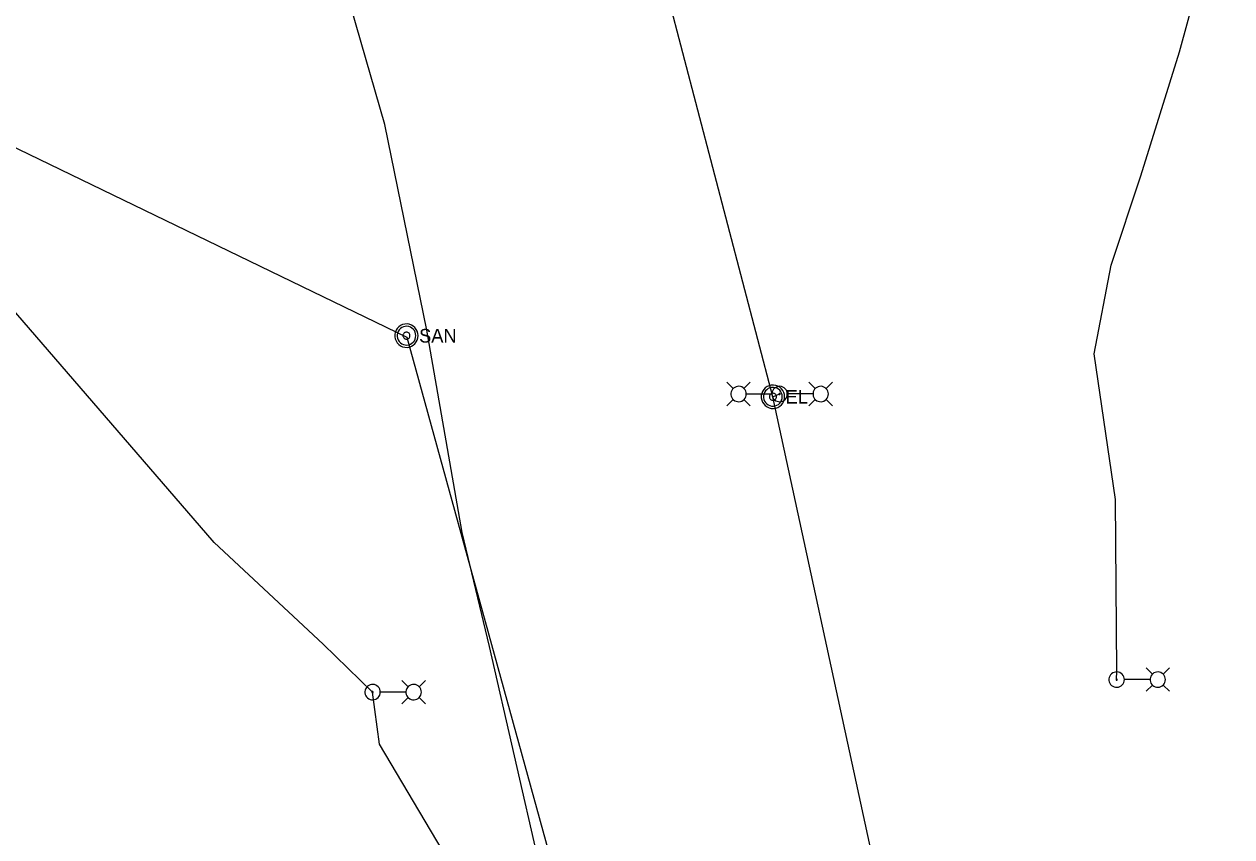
# Model space of a CAD drawing. Extents: x 600849 to 606371, y 330010 to 403088.
# Drawn here: x 603977.3 to 604318, y 348996 to 349225.2 of the extents above; entities that cross this region are included whole.
import ezdxf

# ---------------------------------------------------------------- set-up
doc = ezdxf.new("R2010")
doc.units = 0
for name, color, linetype in [('E_FTMS_Conduit', 7, 'Continuous'), ('E_LTG', 7, 'Continuous'), ('E_LTG_CID', 7, 'Continuous'), ('E_UTL_E', 7, 'Continuous'), ('E_UTL_E_UG', 7, 'Continuous'), ('E_UTL_SAN', 7, 'Continuous'), ('E_UTL_SAN_UG', 7, 'Continuous')]:
    doc.layers.add(name, color=color, linetype=linetype)

msp = doc.modelspace()

# ---------------------------------------------------------------- linework, layer by layer
at = {"layer": 'E_FTMS_Conduit'}
msp.add_lwpolyline([(604122.74, 348988.04), (604108.56, 349049.67), (604100.88, 349081.84), (604090.92, 349138.93), (604079.09, 349196.91), (604056.03, 349276.86), (604043.16, 349350.52), (604043.52, 349350.57), (604038.65, 349379.99), (604027.8, 349419.58), (604014.43, 349447.39), (603999.06, 349483.4), (603987.98, 349514.15), (603982.63, 349526.67)], dxfattribs=at)
at = {"layer": 'E_LTG'}
for points in [[(604177.34, 349122.43), (604175.57, 349124.21)], [(604181.04, 349120.91), (604181, 349121.32), (604180.89, 349121.71), (604180.7, 349122.08), (604180.44, 349122.41), (604180.13, 349122.68), (604179.77, 349122.89), (604179.38, 349123.02), (604178.97, 349123.08), (604178.56, 349123.06), (604178.16, 349122.96), (604177.78, 349122.79), (604177.44, 349122.55), (604177.16, 349122.25), (604176.93, 349121.9), (604176.78, 349121.52), (604176.7, 349121.11), (604176.7, 349120.7), (604176.78, 349120.29), (604176.93, 349119.91), (604177.16, 349119.56), (604177.44, 349119.26), (604177.78, 349119.02), (604178.16, 349118.85), (604178.56, 349118.75), (604178.97, 349118.73), (604179.38, 349118.79), (604179.77, 349118.93), (604180.13, 349119.13), (604180.44, 349119.4), (604180.7, 349119.73), (604180.89, 349120.1), (604181, 349120.49), (604181.04, 349120.91)], [(604180.39, 349122.43), (604182.17, 349124.21)], [(604192.61, 349120.91), (604192.57, 349121.32), (604192.45, 349121.71), (604192.26, 349122.08), (604192.01, 349122.41), (604191.69, 349122.68), (604191.34, 349122.88), (604190.95, 349123.02), (604190.54, 349123.08), (604190.12, 349123.06), (604189.72, 349122.96), (604189.34, 349122.79), (604189.01, 349122.55), (604188.72, 349122.25), (604188.5, 349121.9), (604188.35, 349121.52), (604188.27, 349121.11), (604188.27, 349120.7), (604188.35, 349120.29), (604188.5, 349119.91), (604188.72, 349119.56), (604189.01, 349119.26), (604189.34, 349119.02), (604189.72, 349118.85), (604190.12, 349118.75), (604190.54, 349118.73), (604190.95, 349118.79), (604191.34, 349118.93), (604191.69, 349119.13), (604192.01, 349119.4), (604192.26, 349119.73), (604192.45, 349120.1), (604192.57, 349120.49), (604192.61, 349120.91)], [(604200.51, 349122.43), (604198.74, 349124.21)], [(604204.21, 349120.91), (604204.17, 349121.32), (604204.06, 349121.71), (604203.87, 349122.08), (604203.61, 349122.41), (604203.3, 349122.68), (604202.94, 349122.88), (604202.55, 349123.02), (604202.14, 349123.08), (604201.73, 349123.06), (604201.32, 349122.96), (604200.95, 349122.79), (604200.61, 349122.55), (604200.33, 349122.25), (604200.1, 349121.9), (604199.95, 349121.52), (604199.87, 349121.11), (604199.87, 349120.7), (604199.95, 349120.29), (604200.1, 349119.91), (604200.33, 349119.56), (604200.61, 349119.26), (604200.95, 349119.02), (604201.32, 349118.85), (604201.73, 349118.75), (604202.14, 349118.73), (604202.55, 349118.79), (604202.94, 349118.93), (604203.3, 349119.13), (604203.61, 349119.4), (604203.87, 349119.73), (604204.06, 349120.1), (604204.17, 349120.49), (604204.21, 349120.91)], [(604203.56, 349122.43), (604205.34, 349124.21)], [(604181.08, 349120.91), (604188.26, 349120.91)], [(604190.6, 349120.91), (604190.6, 349120.94), (604190.59, 349120.97), (604190.57, 349121), (604190.55, 349121.02), (604190.53, 349121.04), (604190.5, 349121.06), (604190.47, 349121.07), (604190.44, 349121.07), (604190.41, 349121.07), (604190.38, 349121.06), (604190.35, 349121.05), (604190.32, 349121.03), (604190.3, 349121.01), (604190.28, 349120.98), (604190.27, 349120.95), (604190.27, 349120.92), (604190.27, 349120.89), (604190.27, 349120.86), (604190.28, 349120.83), (604190.3, 349120.8), (604190.32, 349120.78), (604190.35, 349120.76), (604190.38, 349120.75), (604190.41, 349120.74), (604190.44, 349120.74), (604190.47, 349120.74), (604190.5, 349120.75), (604190.53, 349120.77), (604190.55, 349120.79), (604190.57, 349120.82), (604190.59, 349120.84), (604190.6, 349120.87), (604190.6, 349120.91)], [(604199.82, 349120.91), (604192.65, 349120.91)], [(604177.34, 349119.38), (604175.57, 349117.61)], [(604180.39, 349119.38), (604182.17, 349117.61)], [(604200.51, 349119.38), (604198.74, 349117.61)], [(604203.56, 349119.38), (604205.34, 349117.61)], [(604287.72, 349040.34), (604287.68, 349040.75), (604287.56, 349041.15), (604287.37, 349041.52), (604287.11, 349041.84), (604286.8, 349042.11), (604286.44, 349042.32), (604286.05, 349042.45), (604285.64, 349042.51), (604285.23, 349042.49), (604284.83, 349042.39), (604284.45, 349042.22), (604284.12, 349041.98), (604283.83, 349041.68), (604283.61, 349041.34), (604283.45, 349040.95), (604283.37, 349040.55), (604283.37, 349040.13), (604283.45, 349039.73), (604283.61, 349039.34), (604283.83, 349038.99), (604284.12, 349038.69), (604284.45, 349038.45), (604284.83, 349038.28), (604285.23, 349038.19), (604285.64, 349038.17), (604286.05, 349038.22), (604286.44, 349038.36), (604286.8, 349038.57), (604287.11, 349038.84), (604287.37, 349039.16), (604287.56, 349039.53), (604287.68, 349039.93), (604287.72, 349040.34)], [(604295.62, 349041.86), (604293.84, 349043.64)], [(604299.32, 349040.34), (604299.28, 349040.75), (604299.16, 349041.15), (604298.97, 349041.52), (604298.72, 349041.84), (604298.41, 349042.11), (604298.05, 349042.32), (604297.66, 349042.45), (604297.25, 349042.51), (604296.83, 349042.49), (604296.43, 349042.39), (604296.06, 349042.22), (604295.72, 349041.98), (604295.43, 349041.68), (604295.21, 349041.34), (604295.06, 349040.95), (604294.98, 349040.55), (604294.98, 349040.13), (604295.06, 349039.73), (604295.21, 349039.34), (604295.43, 349038.99), (604295.72, 349038.69), (604296.06, 349038.45), (604296.43, 349038.28), (604296.83, 349038.19), (604297.25, 349038.17), (604297.66, 349038.22), (604298.05, 349038.36), (604298.41, 349038.57), (604298.72, 349038.84), (604298.97, 349039.16), (604299.16, 349039.53), (604299.28, 349039.93), (604299.32, 349040.34)], [(604298.67, 349041.86), (604300.45, 349043.64)], [(604077.77, 349036.8), (604077.73, 349037.21), (604077.61, 349037.61), (604077.42, 349037.98), (604077.16, 349038.3), (604076.85, 349038.57), (604076.49, 349038.78), (604076.1, 349038.92), (604075.69, 349038.98), (604075.28, 349038.96), (604074.88, 349038.86), (604074.5, 349038.69), (604074.17, 349038.45), (604073.88, 349038.15), (604073.66, 349037.8), (604073.5, 349037.41), (604073.42, 349037.01), (604073.42, 349036.6), (604073.5, 349036.19), (604073.66, 349035.8), (604073.88, 349035.46), (604074.17, 349035.16), (604074.5, 349034.92), (604074.88, 349034.75), (604075.28, 349034.65), (604075.69, 349034.63), (604076.1, 349034.69), (604076.49, 349034.82), (604076.85, 349035.03), (604077.16, 349035.3), (604077.42, 349035.63), (604077.61, 349035.99), (604077.73, 349036.39), (604077.77, 349036.8)], [(604085.67, 349038.33), (604083.89, 349040.1)], [(604089.37, 349036.8), (604089.33, 349037.21), (604089.21, 349037.61), (604089.02, 349037.98), (604088.77, 349038.3), (604088.46, 349038.57), (604088.1, 349038.78), (604087.71, 349038.92), (604087.3, 349038.98), (604086.88, 349038.96), (604086.48, 349038.86), (604086.11, 349038.69), (604085.77, 349038.45), (604085.48, 349038.15), (604085.26, 349037.8), (604085.11, 349037.41), (604085.03, 349037.01), (604085.03, 349036.6), (604085.11, 349036.19), (604085.26, 349035.8), (604085.48, 349035.46), (604085.77, 349035.16), (604086.11, 349034.92), (604086.48, 349034.75), (604086.88, 349034.65), (604087.3, 349034.63), (604087.71, 349034.69), (604088.1, 349034.82), (604088.46, 349035.03), (604088.77, 349035.3), (604089.02, 349035.63), (604089.21, 349035.99), (604089.33, 349036.39), (604089.37, 349036.8)], [(604088.72, 349038.33), (604090.49, 349040.1)], [(604285.71, 349040.34), (604285.7, 349040.37), (604285.69, 349040.4), (604285.68, 349040.43), (604285.66, 349040.45), (604285.64, 349040.47), (604285.61, 349040.49), (604285.58, 349040.5), (604285.55, 349040.51), (604285.52, 349040.5), (604285.49, 349040.5), (604285.46, 349040.48), (604285.43, 349040.46), (604285.41, 349040.44), (604285.39, 349040.42), (604285.38, 349040.39), (604285.37, 349040.35), (604285.37, 349040.32), (604285.38, 349040.29), (604285.39, 349040.26), (604285.41, 349040.24), (604285.43, 349040.21), (604285.46, 349040.19), (604285.49, 349040.18), (604285.52, 349040.17), (604285.55, 349040.17), (604285.58, 349040.18), (604285.61, 349040.19), (604285.64, 349040.2), (604285.66, 349040.22), (604285.68, 349040.25), (604285.69, 349040.28), (604285.7, 349040.31), (604285.71, 349040.34)], [(604294.93, 349040.34), (604287.75, 349040.34)], [(604295.62, 349038.82), (604293.84, 349037.04)], [(604298.67, 349038.82), (604300.45, 349037.04)], [(604075.76, 349036.8), (604075.75, 349036.83), (604075.74, 349036.86), (604075.73, 349036.89), (604075.71, 349036.92), (604075.69, 349036.94), (604075.66, 349036.95), (604075.63, 349036.96), (604075.6, 349036.97), (604075.57, 349036.97), (604075.54, 349036.96), (604075.51, 349036.95), (604075.48, 349036.93), (604075.46, 349036.9), (604075.44, 349036.88), (604075.43, 349036.85), (604075.42, 349036.82), (604075.42, 349036.79), (604075.43, 349036.75), (604075.44, 349036.73), (604075.46, 349036.7), (604075.48, 349036.68), (604075.51, 349036.66), (604075.54, 349036.64), (604075.57, 349036.64), (604075.6, 349036.64), (604075.63, 349036.64), (604075.66, 349036.65), (604075.69, 349036.67), (604075.71, 349036.69), (604075.73, 349036.71), (604075.74, 349036.74), (604075.75, 349036.77), (604075.76, 349036.8)], [(604084.98, 349036.8), (604077.8, 349036.8)], [(604085.67, 349035.28), (604083.89, 349033.5)], [(604088.72, 349035.28), (604090.49, 349033.5)]]:
    msp.add_lwpolyline(points, dxfattribs=at)
at = {"layer": 'E_LTG_CID'}
for points in [[(604318.05, 348339.7), (604287.36, 348606.91), (604242.16, 348872.6), (604188.57, 349120.13), (604125.01, 349362.84), (604050.82, 349602.08), (604014.23, 349708.06), (603966.43, 349837.54), (603869.82, 350091.09), (603838.85, 350172.22), (603784.41, 350315.72), (603699.29, 350539.43), (603613.87, 350764.2), (603510.34, 351036.54), (603442.84, 351213.06), (603357.76, 351436.96)], [(604285.54, 349040.34), (604285.57, 349042.77), (604285.23, 349091.18), (604279.19, 349132.21), (604283.97, 349157.26), (604292.37, 349182.41), (604303.3, 349217.41), (604310.86, 349245.32)], [(604177.44, 348812.79), (604175.61, 348813.39), (604162.29, 348830.79), (604147.42, 348861.43), (604138.4, 348891.47), (604103.33, 348978.71), (604077.58, 349022.17), (604075.59, 349036.8), (604061.65, 349050.32), (604030.89, 349079), (603967.67, 349152.06), (603951.25, 349172.14), (603937.49, 349182.11), (603904.88, 349203.77)]]:
    msp.add_lwpolyline(points, dxfattribs=at)
at = {"layer": 'E_UTL_E'}
for points in [[(604191.87, 349120.13), (604191.81, 349120.75), (604191.64, 349121.36), (604191.35, 349121.91), (604190.96, 349122.41), (604190.49, 349122.82), (604189.94, 349123.13), (604189.35, 349123.34), (604188.73, 349123.43), (604188.1, 349123.4), (604187.49, 349123.25), (604186.92, 349122.99), (604186.41, 349122.62), (604185.98, 349122.17), (604185.64, 349121.64), (604185.41, 349121.06), (604185.29, 349120.44), (604185.29, 349119.82), (604185.41, 349119.2), (604185.64, 349118.62), (604185.98, 349118.09), (604186.41, 349117.63), (604186.92, 349117.27), (604187.49, 349117.01), (604188.1, 349116.86), (604188.73, 349116.83), (604189.35, 349116.92), (604189.94, 349117.13), (604190.49, 349117.44), (604190.96, 349117.85), (604191.35, 349118.34), (604191.64, 349118.9), (604191.81, 349119.5), (604191.87, 349120.13)], [(604191.87, 349120.13), (604191.81, 349120.75), (604191.64, 349121.36), (604191.35, 349121.91), (604190.96, 349122.41), (604190.49, 349122.82), (604189.94, 349123.13), (604189.35, 349123.34), (604188.73, 349123.43), (604188.1, 349123.4), (604187.49, 349123.25), (604186.92, 349122.99), (604186.41, 349122.62), (604185.98, 349122.17), (604185.64, 349121.64), (604185.41, 349121.06), (604185.29, 349120.44), (604185.29, 349119.82), (604185.41, 349119.2), (604185.64, 349118.62), (604185.98, 349118.09), (604186.41, 349117.63), (604186.92, 349117.27), (604187.49, 349117.01), (604188.1, 349116.86), (604188.73, 349116.83), (604189.35, 349116.92), (604189.94, 349117.13), (604190.49, 349117.44), (604190.96, 349117.85), (604191.35, 349118.34), (604191.64, 349118.9), (604191.81, 349119.5), (604191.87, 349120.13)], [(604191.21, 349120.13), (604191.16, 349120.63), (604191.02, 349121.11), (604190.79, 349121.56), (604190.48, 349121.95), (604190.1, 349122.28), (604189.67, 349122.53), (604189.19, 349122.69), (604188.7, 349122.77), (604188.2, 349122.74), (604187.71, 349122.62), (604187.25, 349122.42), (604186.84, 349122.12), (604186.5, 349121.76), (604186.23, 349121.34), (604186.04, 349120.87), (604185.94, 349120.38), (604185.94, 349119.88), (604186.04, 349119.39), (604186.23, 349118.92), (604186.5, 349118.5), (604186.84, 349118.13), (604187.25, 349117.84), (604187.71, 349117.63), (604188.2, 349117.52), (604188.7, 349117.49), (604189.19, 349117.56), (604189.67, 349117.73), (604190.1, 349117.98), (604190.48, 349118.31), (604190.79, 349118.7), (604191.02, 349119.15), (604191.16, 349119.63), (604191.21, 349120.13)], [(604191.21, 349120.13), (604191.16, 349120.63), (604191.02, 349121.11), (604190.79, 349121.56), (604190.48, 349121.95), (604190.1, 349122.28), (604189.67, 349122.53), (604189.19, 349122.69), (604188.7, 349122.77), (604188.2, 349122.74), (604187.71, 349122.62), (604187.25, 349122.42), (604186.84, 349122.12), (604186.5, 349121.76), (604186.23, 349121.34), (604186.04, 349120.87), (604185.94, 349120.38), (604185.94, 349119.88), (604186.04, 349119.39), (604186.23, 349118.92), (604186.5, 349118.5), (604186.84, 349118.13), (604187.25, 349117.84), (604187.71, 349117.63), (604188.2, 349117.52), (604188.7, 349117.49), (604189.19, 349117.56), (604189.67, 349117.73), (604190.1, 349117.98), (604190.48, 349118.31), (604190.79, 349118.7), (604191.02, 349119.15), (604191.16, 349119.63), (604191.21, 349120.13)], [(604189.56, 349120.13), (604189.54, 349120.32), (604189.49, 349120.5), (604189.41, 349120.66), (604189.29, 349120.81), (604189.15, 349120.94), (604188.98, 349121.03), (604188.81, 349121.09), (604188.62, 349121.12), (604188.43, 349121.11), (604188.25, 349121.06), (604188.08, 349120.99), (604187.92, 349120.88), (604187.79, 349120.74), (604187.69, 349120.58), (604187.62, 349120.41), (604187.59, 349120.22), (604187.59, 349120.03), (604187.62, 349119.85), (604187.69, 349119.68), (604187.79, 349119.52), (604187.92, 349119.38), (604188.08, 349119.27), (604188.25, 349119.19), (604188.43, 349119.15), (604188.62, 349119.14), (604188.81, 349119.17), (604188.98, 349119.23), (604189.15, 349119.32), (604189.29, 349119.45), (604189.41, 349119.59), (604189.49, 349119.76), (604189.54, 349119.94), (604189.56, 349120.13)], [(604189.56, 349120.13), (604189.54, 349120.32), (604189.49, 349120.5), (604189.41, 349120.66), (604189.29, 349120.81), (604189.15, 349120.94), (604188.98, 349121.03), (604188.81, 349121.09), (604188.62, 349121.12), (604188.43, 349121.11), (604188.25, 349121.06), (604188.08, 349120.99), (604187.92, 349120.88), (604187.79, 349120.74), (604187.69, 349120.58), (604187.62, 349120.41), (604187.59, 349120.22), (604187.59, 349120.03), (604187.62, 349119.85), (604187.69, 349119.68), (604187.79, 349119.52), (604187.92, 349119.38), (604188.08, 349119.27), (604188.25, 349119.19), (604188.43, 349119.15), (604188.62, 349119.14), (604188.81, 349119.17), (604188.98, 349119.23), (604189.15, 349119.32), (604189.29, 349119.45), (604189.41, 349119.59), (604189.49, 349119.76), (604189.54, 349119.94), (604189.56, 349120.13)]]:
    msp.add_lwpolyline(points, dxfattribs=at)
at = {"layer": 'E_UTL_E_UG'}
msp.add_lwpolyline([(604188.57, 349120.13), (604190.43, 349120.91)], dxfattribs=at)
at = {"layer": 'E_UTL_SAN'}
for points in [[(604088.47, 349137.37), (604088.41, 349137.99), (604088.23, 349138.59), (604087.94, 349139.15), (604087.55, 349139.65), (604087.08, 349140.06), (604086.54, 349140.37), (604085.94, 349140.57), (604085.32, 349140.66), (604084.7, 349140.63), (604084.09, 349140.49), (604083.52, 349140.23), (604083.01, 349139.86), (604082.57, 349139.41), (604082.23, 349138.88), (604082, 349138.3), (604081.88, 349137.68), (604081.88, 349137.05), (604082, 349136.44), (604082.23, 349135.86), (604082.57, 349135.33), (604083.01, 349134.87), (604083.52, 349134.51), (604084.09, 349134.25), (604084.7, 349134.1), (604085.32, 349134.07), (604085.94, 349134.16), (604086.54, 349134.37), (604087.08, 349134.68), (604087.55, 349135.09), (604087.94, 349135.58), (604088.23, 349136.14), (604088.41, 349136.74), (604088.47, 349137.37)], [(604087.81, 349137.37), (604087.76, 349137.87), (604087.62, 349138.35), (604087.39, 349138.8), (604087.08, 349139.19), (604086.7, 349139.52), (604086.26, 349139.77), (604085.79, 349139.93), (604085.29, 349140), (604084.79, 349139.98), (604084.3, 349139.86), (604083.85, 349139.65), (604083.44, 349139.36), (604083.09, 349139), (604082.82, 349138.58), (604082.63, 349138.11), (604082.54, 349137.62), (604082.54, 349137.12), (604082.63, 349136.62), (604082.82, 349136.16), (604083.09, 349135.74), (604083.44, 349135.37), (604083.85, 349135.08), (604084.3, 349134.87), (604084.79, 349134.75), (604085.29, 349134.73), (604085.79, 349134.8), (604086.26, 349134.97), (604086.7, 349135.22), (604087.08, 349135.55), (604087.39, 349135.94), (604087.62, 349136.39), (604087.76, 349136.87), (604087.81, 349137.37)], [(604086.16, 349137.37), (604086.14, 349137.56), (604086.09, 349137.74), (604086, 349137.9), (604085.88, 349138.05), (604085.74, 349138.17), (604085.58, 349138.27), (604085.4, 349138.33), (604085.21, 349138.36), (604085.03, 349138.35), (604084.84, 349138.3), (604084.67, 349138.23), (604084.52, 349138.12), (604084.39, 349137.98), (604084.29, 349137.82), (604084.22, 349137.65), (604084.18, 349137.46), (604084.18, 349137.27), (604084.22, 349137.09), (604084.29, 349136.91), (604084.39, 349136.76), (604084.52, 349136.62), (604084.67, 349136.51), (604084.84, 349136.43), (604085.03, 349136.39), (604085.21, 349136.38), (604085.4, 349136.41), (604085.58, 349136.47), (604085.74, 349136.56), (604085.88, 349136.68), (604086, 349136.83), (604086.09, 349137), (604086.14, 349137.18), (604086.16, 349137.37)]]:
    msp.add_lwpolyline(points, dxfattribs=at)
at = {"layer": 'E_UTL_SAN_UG'}
for p, q in [((604085.38, 349136.89), (603922.99, 349215.39)), ((604181.34, 348788.4), (604085.38, 349136.89))]:
    msp.add_line(p, q, dxfattribs=at)

# ---------------------------------------------------------------- texts
at = {"layer": 'E_UTL_E'}
msp.add_text('EL', height=3.849, dxfattribs=at).set_placement((604192.14, 349118.18))
msp.add_text('EL', height=3.849, dxfattribs=at).set_placement((604192.14, 349118.18))
at = {"layer": 'E_UTL_SAN'}
msp.add_text('SAN', height=3.849, dxfattribs=at).set_placement((604088.73, 349135.42))

doc.saveas('drawing.dxf')
